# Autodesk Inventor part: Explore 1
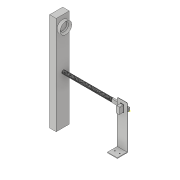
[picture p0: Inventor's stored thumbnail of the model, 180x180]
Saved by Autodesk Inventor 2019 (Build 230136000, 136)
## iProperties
Created: 2020-02
Part Number: Explore 1
Material: Generic
Document SubType Name: Modeling
Designer: Naveen G
Density: 1 g/cm^3
Appearance: Default
Author: Naveen G
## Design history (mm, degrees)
sketch "Sketch1"
  geometry: L1 (0, 0)-(-50, 0); L2 (-50, 0)-(-50, 10); L3 (-50, 10)-(0, 10); L4 (0, 10)-(0, 0)
  constraints: 8 end point, 2 parallel, 1 horizontal, 1 perpendicular
  dimensions: "d0" = 50 distance of L2.end L3.end; "d1" = 10 distance of L1.end L2.end
extrude "Extrusion1" new body sketch "Sketch1" distance "d2" = 5; taper "d3" = 0 deg
sketch "Sketch2" dims "d6" = 2.5
  geometry: L1 (0, 0)-(0, 10) reference; L2 (0, 0)-(0, 5); L3 (-13.75, 5)-(-15, 5); 1 further point
  constraints: 4 end point, 1 coincident, 1 horizontal alignment, 1 midpoint, 1 perpendicular, 2 other
  dimensions: "d4" = 5 distance of L1.start L2.end (derived); "d5" = 15 distance of L2.end L3.end
extrude "Extrusion2" join sketch "Sketch2" distance "d7" = 1; taper "d8" = 0 deg
sketch "Sketch3"
  geometry: C1 r 1.25 at (0, 0) reference; C2 r 1 at (0, 0); 1 further point
  constraints: 1 centre point, 1 coincident
  dimensions: "d9" = 2 diameter of C2
extrude "Extrusion3" join sketch "Sketch3" distance "d10" = 1; taper "d11" = 0 deg
sketch "Sketch4"
  geometry: L1 (0, 0)-(15, 0); L2 (15, -5)-(15, 5) reference; L3 (15, 0)-(15, 20); L4 (15, 20)-(15, -130); L5 (15, -130)-(-15, -130); L6 (-15, -130)-(-15, 20); L7 (-15, 20)-(15, 20); C1 r 1 at (0, 0) reference
  constraints: 12 end point, 1 collinear, 1 horizontal, 1 midpoint, 1 perpendicular, 1 point on line
  dimensions: "d12" = 15 distance of L1.start L1.end (derived); "d13" = 20 distance of L1.end L3.end; "d14" = 150 distance of L3.end L4.end; "d15" = 30 distance of L4.end L5.end; "d16" = 150 distance of L5.end L6.end; "d17" = 30 distance of L6.end L3.end (derived)
extrude "Extrusion4" join sketch "Sketch4" distance "d18" = 1; taper "d19" = 0 deg
sketch "Sketch5"
  geometry: C1 r 1 at (0, 0); 1 further point
  constraints: 1 centre point
extrude "Extrusion5" join sketch "Sketch5" distance "d20" = 1; taper "d21" = 0 deg
sketch "Sketch6"
  geometry: L1 (-15, -130)-(15, -130) reference; L2 (-15, -130)-(15, -130); L3 (15, -130)-(15, -129); L4 (15, -129)-(-15, -129); L5 (-15, -129)-(-15, -130); 1 further point
  constraints: 8 end point, 2 parallel, 1 horizontal, 1 perpendicular
  dimensions: "d22" = 30 distance of L4.end L3.end; "d23" = 1 distance of L3.end L2.end
extrude "Extrusion6" join sketch "Sketch6" distance "d24" = 50; taper "d25" = 0 deg
sketch "Sketch7"
  geometry: L1 (0, -50)-(30, -50) reference; L2 (0, -50)-(0, -30); L3 (0, 1)-(0, -50) reference; L4 (0, -30)-(30, -30); L5 (0, -30)-(7.5, -30); L6 (7.5, -30)-(30, -30); L7 (30, -30)-(22.5, -30); C1 r 1.25 at (7.5, -30); C2 r 1.25 at (22.5, -30); 1 further point
  constraints: 10 end point, 3 point on line, 2 centre point, 2 coincident, 1 collinear, 1 perpendicular
  dimensions: "d26" = 20 distance of L1.start L2.end; "d27" = 7.5 distance of L2.end L5.end; "d28" = 7.5 distance of L4.end L7.end; "d29" = 2.5 diameter of C1; "d30" = 2.5 diameter of C2
extrude "Extrusion7" cut sketch "Sketch7" extent not by distance; stored distance "d31" = 0; taper "d32" = 0 deg
sketch "Sketch8"
  geometry: L1 (0, 0)-(5.5, 0); L2 (5.5, 0)-(5.5, 10.5); L3 (5.5, 10.5)-(-5.5, 10.5); L4 (-5.5, 10.5)-(-5.5, -10.5); L5 (-5.5, -10.5)-(5.5, -10.5); L6 (5.5, -10.5)-(5.5, 0); L7 (-35, -5)-(15, -5) reference; C1 r 1 at (0, 0) reference
  constraints: 12 end point, 4 perpendicular, 1 horizontal, 1 point on line
  dimensions: "d33" = 5.5 distance of L1.start L1.end; "d34" = 10.5 distance of L1.end L2.end; "d35" = 11 distance of L2.end L3.end; "d36" = 21 distance of L3.end L4.end; "d37" = 11 distance of L4.end L5.end
extrude "Extrusion8" join sketch "Sketch8" distance "d38" = 1; taper "d39" = 0 deg
sketch "Sketch9"
  geometry: L1 (0, 0)-(5, 0); L2 (5, 0)-(5, 10); L3 (5, 10)-(-5, 10); L4 (-5.5, 10.5)-(-5.5, -10.5) reference; L5 (-5, 10)-(-5, -10); L6 (-5, -10)-(5, -10); L7 (5, -10)-(5, 0); 1 further point
  constraints: 12 end point, 3 perpendicular, 1 horizontal, 1 point on line
  dimensions: "d40" = 5 distance of L1.start L1.end; "d41" = 10 distance of L1.end L2.end; "d42" = 10 distance of L2.end L3.end; "d43" = 20 distance of L3.end L5.end; "d44" = 10 distance of L5.end L6.end
extrude "Extrusion9" join sketch "Sketch9" distance "d45" = 12; taper "d46" = 0 deg
chamfer "Chamfer1" distance "d47" = 1.25; stored, may be unused: second distance "d48" = 1.25, angle "d49" = 45 deg
fillet "Fillet1" dims "d50" = 2
fillet "Fillet2" dims "d51" = 2
sketch "Sketch10"
  geometry: L1 (-5.5, 10.5)-(5.5, 10.5) reference; L2 (0, 10.5)-(2.5, 10.5); L3 (2.5, 10.5)-(-2.5, 10.5); L4 (-2.5, 10.5)-(0, 10.5); L5 (-3.4, 10.5)-(-1.6, 10.5); L6 (1.6, 10.5)-(3.4, 10.5); L7 (5.5, -10.5)-(-5.5, -10.5) reference; L8 (-1.6, -10.5)-(-2.5, -10.5); L9 (-2.5, -10.5)-(0, -10.5); L10 (1.6, -10.5)-(2.5, -10.5); L11 (2.5, -10.5)-(1.6, -10.5); A1 r 0.9 centre (-2.5, 10.5) between (-1.6, 10.5) and (-3.4, 10.5); A2 r 0.9 centre (2.5, 10.5) between (3.4, 10.5) and (1.6, 10.5); A3 r 0.9 centre (-2.5, -10.5) between (-3.4, -10.5) and (-1.6, -10.5); A4 r 0.9 centre (2.5, -10.5) between (1.6, -10.5) and (3.4, -10.5); 1 further point
  constraints: 18 end point, 11 point on line, 8 point on circle, 5 collinear, 4 centre point, 4 coincident, 2 midpoint
  dimensions: "d52" = 2.5 distance of L2.start L2.end; "d53" = 5 distance of L2.end L3.end; "d54" = 1.8 diameter of A1; "d55" = 1.8 diameter of A2; "d56" = 2.5 distance of L9.end L8.end; "d57" = 2.5 distance of L9.end L10.end; "d58" = 1.8 diameter of A3; "d59" = 1.8 diameter of A4
extrude "Extrusion10" join sketch "Sketch10" distance "d60" = 1; taper "d61" = 0 deg
sketch "Sketch11"
  geometry: L1 (-5.5, -10.5)-(5.5, -10.5) reference; L2 (0, -10.5)-(2.5, -10.5); L3 (2.5, -10.5)-(-2.5, -10.5); L4 (-2.5, -10.5)-(0, -10.5); L5 (-3.4, -10.5)-(-1.6, -10.5); L6 (1.6, -10.5)-(3.4, -10.5); A1 r 0.9 centre (-2.5, -10.5) between (-3.4, -10.5) and (-1.6, -10.5); A2 r 0.9 centre (2.5, -10.5) between (1.6, -10.5) and (3.4, -10.5); 1 further point
  constraints: 10 end point, 6 point on line, 4 point on circle, 2 centre point, 2 coincident, 1 collinear, 1 midpoint
  dimensions: "d62" = 2.5 distance of L2.start L2.end; "d63" = 5 distance of L2.end L3.end; "d64" = 1.8 diameter of A1; "d65" = 1.8 diameter of A2
extrude "Extrusion11" join sketch "Sketch11" distance "d66" = 1; taper "d67" = 0 deg
sketch "Sketch12"
  geometry: C1 r 0.35 at (2.5, -10.597); C2 r 0.35 at (-2.5, -10.597); A1 r 0.9 centre (2.5, -10.5) between (1.6, -10.5) and (3.4, -10.5) reference; A2 r 0.9 centre (-2.5, -10.5) between (-3.4, -10.5) and (-1.6, -10.5) reference; 1 further point
  constraints: 2 centre point
  dimensions: "d68" = 0.7 diameter of C1; "d69" = 0.7 diameter of C2
extrude "Extrusion12" join sketch "Sketch12" distance "d70" = 2; taper "d71" = 0 deg
sketch "Sketch13"
  geometry: L1 (-5.5, 10.5)-(-3.4, 10.5) reference; L2 (-3.4, 10.5)-(-2.835, 10.5); L3 (-2.5, 10.5)-(-2.5, 11.4); L4 (-3.4, 10.5)-(-2.835, 10.5); L5 (-2.165, 10.5)-(-1.6, 10.5); A1 r 0.35 centre (-2.5, 10.601) between (-2.165, 10.5) and (-2.835, 10.5); 1 further point
  constraints: 8 end point, 2 horizontal, 2 perpendicular, 2 point on circle, 1 centre point, 1 point on line
  dimensions: "d72" = 0.9 distance of L1.end L3.start; "d73" = 0.9 distance of L3.start L3.end; "d74" = 0.7 diameter of A1
extrude "Extrusion13" join sketch "Sketch13" distance "d75" = 2; taper "d76" = 0 deg
sketch "Sketch14"
  geometry: L1 (1.6, 10.5)-(-1.6, 10.5) reference; L2 (1.6, 10.5)-(2.5, 10.5); L3 (2.5, 10.5)-(2.5, 10.7); C1 r 0.35 at (2.5, 10.6); 1 further point
  constraints: 4 end point, 1 centre point, 1 horizontal, 1 midpoint, 1 perpendicular
  dimensions: "d77" = 0.9 distance of L1.start L2.end; "d78" = 0.2 distance of L2.end L3.end; "d79" = 0.7 diameter of C1
extrude "Extrusion14" join sketch "Sketch14" distance "d80" = 2; taper "d81" = 0 deg
sketch "Sketch15"
  geometry: L1 (13, 20)-(-13, 20) reference; L2 (0, 20)-(0, -80); L3 (0, 20)-(100, 20); L4 (0, -80)-(-15, -80); L5 (-15, 18)-(-15, -130) reference; L6 (15, -130)-(15, 18) reference; L7 (15, -80)-(0, -80); L8 (-15, -130)-(15, -130) reference; L9 (15, -80)-(15, -130); L10 (15, -130)-(-15, -130); L11 (-15, -130)-(-15, -80); 1 further point
  constraints: 14 end point, 4 perpendicular, 3 point on line, 2 vertical, 1 collinear, 1 horizontal, 1 midpoint
  dimensions: "d82" = 100 distance of L2.start L2.end; "d83" = 90 deg angle of L2 L3 (derived)
extrude "Extrusion15" cut sketch "Sketch15" extent not by distance; stored distance "d84" = 10; taper "d85" = 0 deg
sketch "Sketch16"
  geometry: L1 (15, -80)-(-15, -80) reference; L2 (-15, -80)-(15, -80); L3 (15, -80)-(15, -78); L4 (15, -78)-(-15, -78); L5 (-15, -78)-(-15, -80); 1 further point
  constraints: 8 end point, 2 parallel, 1 horizontal, 1 perpendicular
  dimensions: "d86" = 30 distance of L4.end L3.end; "d87" = 2 distance of L3.end L2.end
extrude "Extrusion16" join sketch "Sketch16" distance "d88" = 30; taper "d89" = 0 deg
sketch "Sketch17"
  geometry: L1 (0, 1)-(0, -30) reference; L2 (0, 0)-(0, -15); L3 (0, -15)-(30, -15); L4 (30, -15)-(22.5, -15); L5 (22.5, -15)-(7.5, -15); C1 r 1.5 at (7.5, -15); C2 r 1.5 at (22.5, -15); 1 further point
  constraints: 8 end point, 4 point on line, 2 centre point, 2 coincident, 1 perpendicular
  dimensions: "d90" = 15 distance of L2.start L2.end; "d91" = 30 distance of L2.end L3.end; "d92" = 7.5 distance of L3.end L4.end; "d93" = 15 distance of L4.end L5.end; "d94" = 3 diameter of C1; "d95" = 3 diameter of C2
extrude "Extrusion17" cut sketch "Sketch17" extent not by distance; stored distance "d96" = 0; taper "d97" = 0 deg
sketch "Sketch18"
  geometry: L1 (30, 0)-(0, 0) reference; L2 (0, 1)-(30, 1) reference; L3 (0, 0)-(30, 0); L4 (30, 0)-(30, 1); L5 (30, 1)-(0, 1); L6 (0, 1)-(0, 0); 1 further point
  constraints: 8 end point, 2 parallel, 1 horizontal, 1 perpendicular
extrude "Extrusion18" join sketch "Sketch18" distance "d98" = 30; taper "d99" = 0 deg
sketch "Sketch19"
  geometry: L1 (0, 0)-(30, 0) reference; L2 (0, 1)-(0, 31) reference; L3 (30, 0)-(0, 0); L4 (0, 0)-(0, 31); L5 (0, 31)-(30, 31); L6 (30, 31)-(30, 0); 1 further point
  constraints: 8 end point, 2 parallel, 1 horizontal, 1 perpendicular
extrude "Extrusion19" join sketch "Sketch19" distance "d100" = 2; taper "d101" = 0 deg
sketch "Sketch20"
  geometry: L1 (30, -31)-(30, -1) reference; L2 (30, -31)-(30, -16); L3 (30, -16)-(0, -16); L4 (0, -16)-(7.5, -16); L5 (7.5, -16)-(22.5, -16); C1 r 1.5 at (22.5, -16); C2 r 1.5 at (7.5, -16); 1 further point
  constraints: 8 end point, 2 centre point, 2 coincident, 2 point on line, 1 midpoint, 1 perpendicular
  dimensions: "d102" = 15 distance of L1.start L2.end (derived); "d103" = 30 distance of L2.end L3.end; "d104" = 7.5 distance of L3.end L4.end; "d105" = 15 distance of L4.end L5.end
extrude "Extrusion20" cut sketch "Sketch20" extent not by distance; stored distance "d106" = 0; taper "d107" = 0 deg
sketch "Sketch21"
  geometry: L1 (-15, -78)-(15, -78) reference; L2 (-15, -80)-(15, -80) reference; L3 (-15, -78)-(15, -78); L4 (15, -78)-(15, -80); L5 (15, -80)-(-15, -80); L6 (-15, -80)-(-15, -78); 1 further point
  constraints: 8 end point, 2 parallel, 1 horizontal, 1 perpendicular
extrude "Extrusion21" cut sketch "Sketch21" extent not by distance; stored distance "d108" = 0; taper "d109" = 0 deg
sketch "Sketch22"
  geometry: L1 (30, 0)-(28, 0) reference; L2 (0, 1)-(30, 1) reference; L3 (30, 0)-(0, 0); L4 (0, 0)-(0, 1); L5 (0, 1)-(30, 1); L6 (30, 1)-(30, 0); 1 further point
  constraints: 8 end point, 2 parallel, 1 horizontal, 1 perpendicular
  dimensions: "d110" = 30 distance of L2.start L5.end (derived)
extrude "Extrusion22" join sketch "Sketch22" distance "d111" = 3; taper "d112" = 0 deg
sketch "Sketch23"
  geometry: 1 further point
sketch "Sketch24"
  geometry: 1 further point
sketch "Sketch25"
  geometry: L1 (0, 0)-(5, 0) reference; L2 (0, 0)-(2.5, 0); L3 (2.5, 0)-(2.5, 5); C1 r 0.25 at (2.5, 5)
  constraints: 4 end point, 1 centre point, 1 coincident, 1 midpoint, 1 perpendicular
  dimensions: "d113" = 5 distance of L2.end L3.end; "d114" = 0.5 diameter of C1
extrude "Extrusion23" join sketch "Sketch25" distance "d115" = 1; taper "d116" = 0 deg
sketch "Sketch26"
  geometry: L1 (-0.174, 0.147)-(0.002, 0.147); L2 (0.002, 0.147)-(0.002, -0.159); L3 (0.002, -0.159)-(-0.174, -0.159); L4 (-0.174, -0.159)-(-0.174, 0.147); 1 further point
  constraints: 8 end point, 2 parallel, 1 horizontal, 1 perpendicular
extrude "Extrusion24" join sketch "Sketch26" distance "d117" = 0.1; taper "d118" = 0 deg
sketch "Sketch27"
  geometry: L1 (0, 0.409)-(0, -0.091) reference; L2 (0, 0.159)-(0, 5.159); C1 r 0.25 at (0, 5.159); 1 further point
  constraints: 2 end point, 1 centre point, 1 coincident, 1 collinear, 1 midpoint
  dimensions: "d119" = 5 distance of L2.start L2.end; "d120" = 0.5 diameter of C1
sketch "Sketch28"
  geometry: L1 (0, 0.409)-(0, -0.091) reference; L2 (0, 0.159)-(-150, 0.159); L3 (-150, 0.159)-(-150, 5.159); C1 r 0.25 at (-150, 5.159); 1 further point
  constraints: 4 end point, 1 centre point, 1 coincident, 1 horizontal, 1 midpoint, 1 vertical
  dimensions: "d121" = 150 distance of L2.start L2.end; "d122" = 5 distance of L2.end L3.end; "d123" = 0.5 diameter of C1
coil "Coil1" sketch "Sketch28" pitch "d124" = 1; turns "d126" = 145; dims "d125" = 10, "d127" = 0, angle "d128" = 90 deg, angle "d129" = 90 deg, "d130" = 0, "d131" = 0
sketch "Sketch29"
  geometry: L1 (0, 0.409)-(0, -0.091) reference; L2 (0, 0.159)-(-50, 0.159); 1 further point
  constraints: 2 end point, 1 horizontal, 1 midpoint
  dimensions: "d132" = 50 distance of L2.start L2.end
sketch "Sketch30"
  geometry: C1 r 0.25 at (0, 0); 1 further point
  constraints: 1 centre point
  dimensions: "d133" = 0.5 diameter of C1
coil "Coil2" sketch "Sketch29", "Sketch30" pitch "d134" = 1; turns "d136" = 5; dims "d135" = 10, "d137" = 0, angle "d138" = 90 deg, angle "d139" = 90 deg, "d140" = 0, "d141" = 0
sketch "Sketch31"
  geometry: L1 (0, 0)-(0, -5); L2 (0, -5)-(0.329, -5); L3 (0.329, -5)-(0.329, -4.544); L4 (0.329, -4.544)-(0, -4.544); L5 (0, -4.544)-(0, -5); 1 further point
  constraints: 10 end point, 2 parallel, 1 horizontal, 1 perpendicular, 1 vertical
  dimensions: "d142" = 5 distance of L1.start L1.end
extrude "Extrusion25" join sketch "Sketch31" distance "d143" = 0.1; taper "d144" = 0 deg
sketch "Sketch32"
  geometry: C1 r 0.25 at (0, 0); 1 further point
  constraints: 1 centre point
  dimensions: "d145" = 0.5 diameter of C1
extrude "Extrusion26" join sketch "Sketch32" distance "d146" = 1; taper "d147" = 0 deg
sketch "Sketch33"
  geometry: L1 (0, -5)-(0.329, -5) reference; L2 (0, -4.544)-(0, -5) reference; L3 (0.329, -5)-(0, -5); L4 (0, -5)-(0, -4.544); L5 (0, -4.544)-(0.329, -4.544); L6 (0.329, -4.544)-(0.329, -5); 1 further point
  constraints: 8 end point, 2 parallel, 1 horizontal, 1 perpendicular
extrude "Extrusion27" cut sketch "Sketch33" extent not by distance; stored distance "d148" = 1; taper "d149" = 0 deg
sketch "Sketch34"
  geometry: L1 (0, -0.159)-(0, 0.147) reference; L2 (0, -0.006)-(20, -0.006); L3 (20, -0.006)-(20, 149.994); L4 (20, 149.994)-(-20, 149.994); L5 (-20, 149.994)-(-20, -150.006); L6 (-20, -150.006)-(20, -150.006); L7 (20, -150.006)-(20, 149.994); 1 further point
  constraints: 12 end point, 3 horizontal, 2 vertical, 1 midpoint
  dimensions: "d150" = 20 distance of L2.start L2.end; "d151" = 150 distance of L2.end L3.end; "d152" = 40 distance of L3.end L4.end; "d153" = 300 distance of L4.end L5.end; "d154" = 40 distance of L5.end L6.end; "d155" = 300 distance of L6.end L3.end (derived)
extrude "Extrusion28" join sketch "Sketch34" distance "d156" = 20; taper "d157" = 0 deg
sketch "Sketch35"
  geometry: L1 (-20, 149.994)-(20, 149.994) reference; L2 (0, 149.994)-(0, 119.994); C1 r 17.5 at (0, 119.994); C2 r 12.5 at (0, 119.994); 1 further point
  constraints: 2 centre point, 2 coincident, 2 end point, 1 midpoint, 1 vertical
  dimensions: "d158" = 30 distance of L2.start L2.end; "d159" = 35 diameter of C1; "d160" = 25 diameter of C2
extrude "Extrusion29" join sketch "Sketch35" distance "d161" = 10; taper "d162" = 0 deg
chamfer "Chamfer2" distance "d163" = 5; stored, may be unused: second distance "d164" = 1.25, angle "d165" = 45 deg
body "Solid1"
